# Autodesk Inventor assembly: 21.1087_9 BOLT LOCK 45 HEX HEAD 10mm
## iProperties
Created: 2007-03
Part Number: 21.1087_9 BOLT LOCK 45 HEX HEAD 10mm
Document SubType Name: Assembly
Designer: Andy Moles
Author: Andy Moles
